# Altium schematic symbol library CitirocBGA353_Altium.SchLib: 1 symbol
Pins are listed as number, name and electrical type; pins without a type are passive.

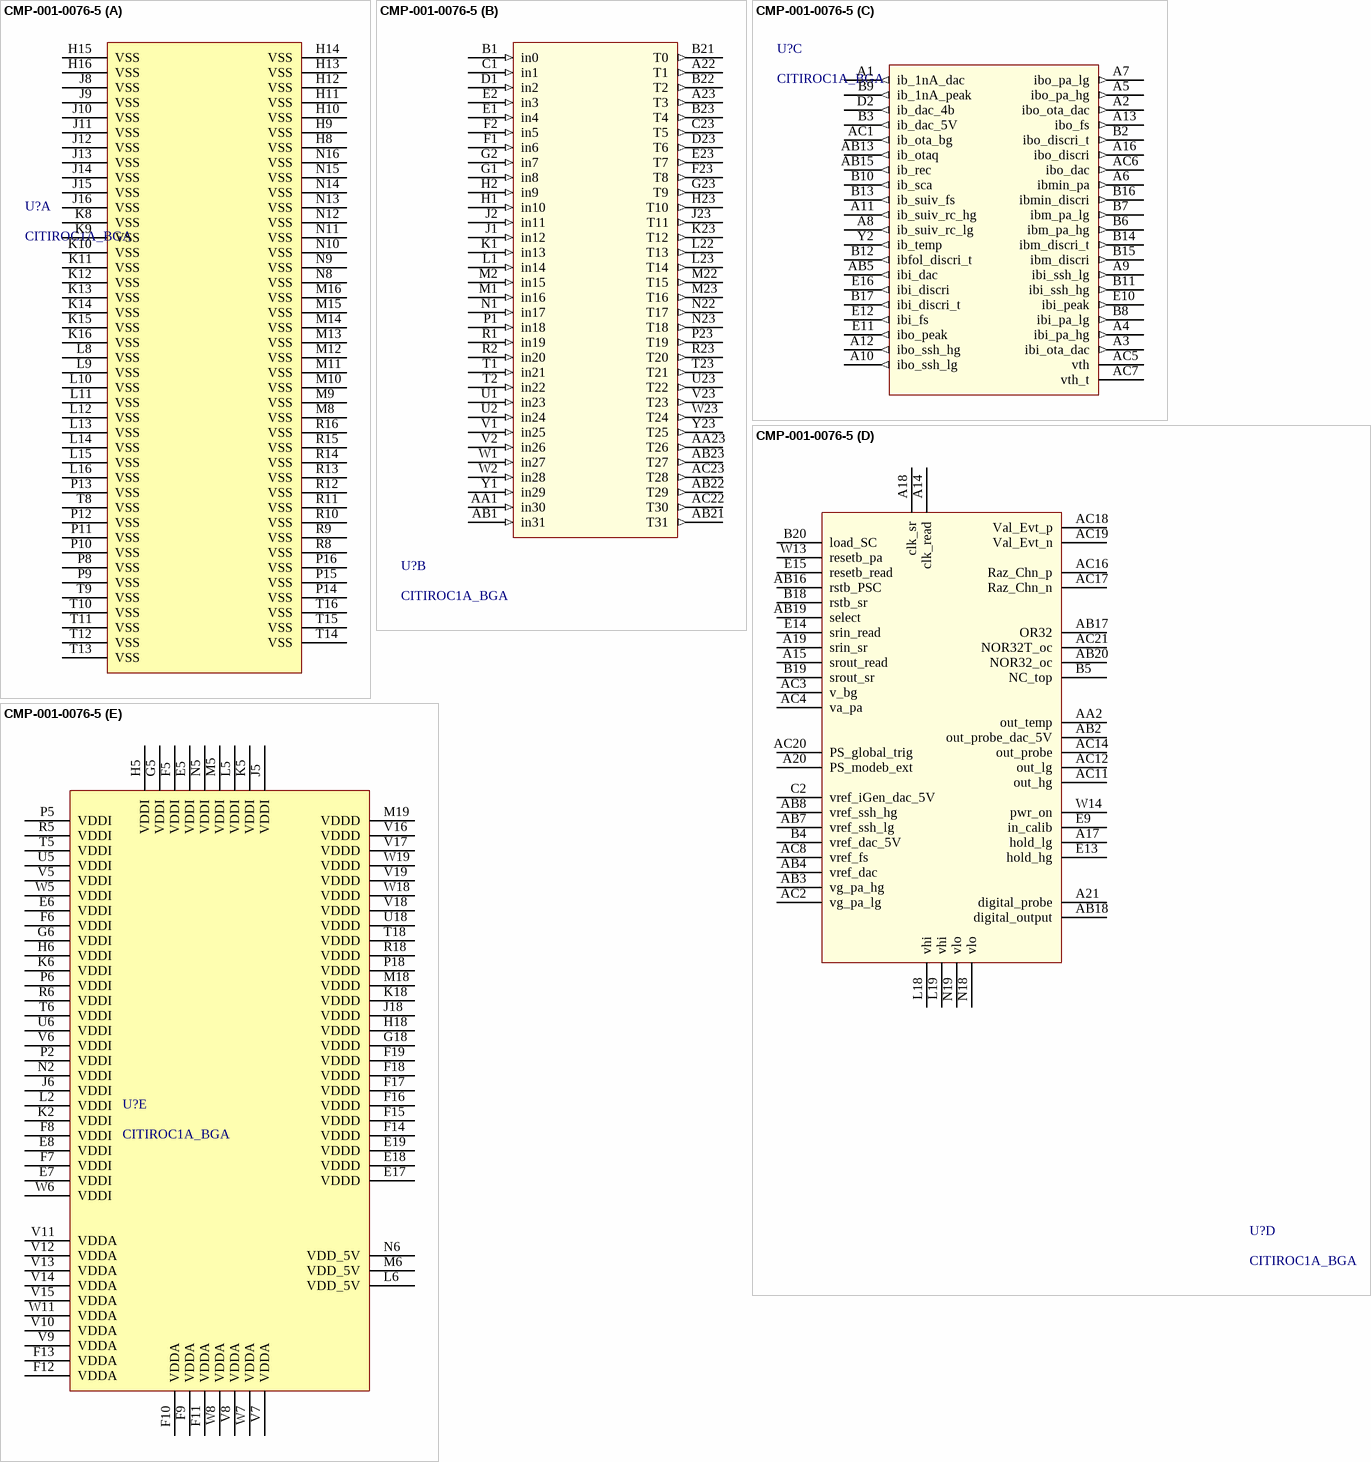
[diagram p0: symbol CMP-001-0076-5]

## CMP-001-0076-5
designator U?, comment CITIROC1A_BGA
Citiroc1A BGA
footprint BGA 353 12mmx12mm (BGA, 353-Leads, Body 12,00x12,00mmx1,20mm, Pitch 0,50mm)
part A pins: H8 VSS (power), H9 VSS (power), H10 VSS (power), H11 VSS (power), H12 VSS (power), H13 VSS (power), H14 VSS (power), H15 VSS (power), H16 VSS (power), J8 VSS (power), J9 VSS (power), J10 VSS (power), J11 VSS (power), J12 VSS (power), J13 VSS (power), J14 VSS (power), J15 VSS (power), J16 VSS (power), K8 VSS (power), K9 VSS (power), K10 VSS (power), K11 VSS (power), K12 VSS (power), K13 VSS (power), K14 VSS (power), K15 VSS (power), K16 VSS (power), L8 VSS (power), L9 VSS (power), L10 VSS (power), L11 VSS (power), L12 VSS (power), L13 VSS (power), L14 VSS (power), L15 VSS (power), L16 VSS (power), M8 VSS (power), M9 VSS (power), M10 VSS (power), M11 VSS (power), M12 VSS (power), M13 VSS (power), M14 VSS (power), M15 VSS (power), M16 VSS (power), N8 VSS (power), N9 VSS (power), N10 VSS (power), N11 VSS (power), N12 VSS (power), N13 VSS (power), N14 VSS (power), N15 VSS (power), N16 VSS (power), P8 VSS (power), P9 VSS (power), P10 VSS (power), P11 VSS (power), P12 VSS (power), P13 VSS (power), P14 VSS (power), P15 VSS (power), P16 VSS (power), R8 VSS (power), R9 VSS (power), R10 VSS (power), R11 VSS (power), R12 VSS (power), R13 VSS (power), R14 VSS (power), R15 VSS (power), R16 VSS (power), T8 VSS (power), T9 VSS (power), T10 VSS (power), T11 VSS (power), T12 VSS (power), T13 VSS (power), T14 VSS (power), T15 VSS (power), T16 VSS (power)
part B pins: A22 T1 (out), A23 T3 (out), AA1 in30 (in), AA23 T26 (out), AB1 in31 (in), AB21 T31 (out), AB22 T29 (out), AB23 T27 (out), AC22 T30 (out), AC23 T28 (out), B1 in0 (in), B21 T0 (out), B22 T2 (out), B23 T4 (out), C1 in1 (in), C23 T5 (out), D1 in2 (in), D23 T6 (out), E1 in4 (in), E2 in3 (in), E23 T7 (out), F1 in6 (in), F2 in5 (in), F23 T8 (out), G1 in8 (in), G2 in7 (in), G23 T9 (out), H1 in10 (in), H2 in9 (in), H23 T10 (out), J1 in12 (in), J2 in11 (in), J23 T11 (out), K1 in13 (in), K23 T12 (out), L1 in14 (in), L22 T13 (out), L23 T14 (out), M1 in16 (in), M2 in15 (in), M22 T15 (out), M23 T16 (out), N1 in17 (in), N22 T17 (out), N23 T18 (out), P1 in18 (in), P23 T19 (out), R1 in19 (in), R2 in20 (in), R23 T20 (out), T1 in21 (in), T2 in22 (in), T23 T21 (out), U1 in23 (in), U2 in24 (in), U23 T22 (out), V1 in25 (in), V2 in26 (in), V23 T23 (out), W1 in27 (in), W2 in28 (in), W23 T24 (out), Y1 in29 (in), Y23 T25 (out)
part C pins: A1 ib_1nA_dac (out), A2 ibo_ota_dac (out), A3 ibi_ota_dac (out), A4 ibi_pa_hg (out), A5 ibo_pa_hg (out), A6 ibmin_pa (out), A7 ibo_pa_lg (out), A8 ib_suiv_rc_lg (out), A9 ibi_ssh_lg (out), A10 ibo_ssh_lg (out), A11 ib_suiv_rc_hg (out), A12 ibo_ssh_hg (out), A13 ibo_fs (out), A16 ibo_discri (out), AB5 ibi_dac (out), AB13 ib_otaq (out), AB15 ib_rec (out), AC1 ib_ota_bg (out), AC5 vth, AC6 ibo_dac (out), AC7 vth_t, B2 ibo_discri_t (out), B3 ib_dac_5V (out), B6 ibm_pa_hg (out), B7 ibm_pa_lg (out), B8 ibi_pa_lg (out), B9 ib_1nA_peak (out), B10 ib_sca (out), B11 ibi_ssh_hg (out), B12 ibfol_discri_t (out), B13 ib_suiv_fs (out), B14 ibm_discri_t (out), B15 ibm_discri (out), B16 ibmin_discri (out), B17 ibi_discri_t (out), D2 ib_dac_4b (out), E10 ibi_peak (out), E11 ibo_peak (out), E12 ibi_fs (out), E16 ibi_discri (out), Y2 ib_temp (out)
part D pins: A14 clk_read, A15 srout_read, A17 hold_lg, A18 clk_sr, A19 srin_sr, A20 PS_modeb_ext, A21 digital_probe, AA2 out_temp, AB2 out_probe_dac_5V, AB3 vg_pa_hg, AB4 vref_dac, AB7 vref_ssh_lg, AB8 vref_ssh_hg, AB16 rstb_PSC, AB17 OR32, AB18 digital_output, AB19 select, AB20 NOR32_oc, AC2 vg_pa_lg, AC3 v_bg, AC4 va_pa, AC8 vref_fs, AC11 out_hg, AC12 out_lg, AC14 out_probe, AC16 Raz_Chn_p, AC17 Raz_Chn_n, AC18 Val_Evt_p, AC19 Val_Evt_n, AC20 PS_global_trig, AC21 NOR32T_oc, B4 vref_dac_5V, B5 NC_top, B18 rstb_sr, B19 srout_sr, B20 load_SC, C2 vref_iGen_dac_5V, E9 in_calib, E13 hold_hg, E14 srin_read, E15 resetb_read, L18 vhi, L19 vhi, N18 vlo, N19 vlo, W13 resetb_pa, W14 pwr_on
part E pins: E5 VDDI (power), E6 VDDI (power), E7 VDDI (power), E8 VDDI (power), E17 VDDD (power), E18 VDDD (power), E19 VDDD (power), F5 VDDI (power), F6 VDDI (power), F7 VDDI (power), F8 VDDI (power), F9 VDDA (power), F10 VDDA (power), F11 VDDA (power), F12 VDDA (power), F13 VDDA (power), F14 VDDD (power), F15 VDDD (power), F16 VDDD (power), F17 VDDD (power), F18 VDDD (power), F19 VDDD (power), G5 VDDI (power), G6 VDDI (power), G18 VDDD (power), H5 VDDI (power), H6 VDDI (power), H18 VDDD (power), J5 VDDI (power), J6 VDDI (power), J18 VDDD (power), K2 VDDI (power), K5 VDDI (power), K6 VDDI (power), K18 VDDD (power), L2 VDDI (power), L5 VDDI (power), L6 VDD_5V (power), M5 VDDI (power), M6 VDD_5V (power), M18 VDDD (power), M19 VDDD (power), N2 VDDI (power), N5 VDDI (power), N6 VDD_5V (power), P2 VDDI (power), P5 VDDI (power), P6 VDDI (power), P18 VDDD (power), R5 VDDI (power), R6 VDDI (power), R18 VDDD (power), T5 VDDI (power), T6 VDDI (power), T18 VDDD (power), U5 VDDI (power), U6 VDDI (power), U18 VDDD (power), V5 VDDI (power), V6 VDDI (power), V7 VDDA (power), V8 VDDA (power), V9 VDDA (power), V10 VDDA (power), V11 VDDA (power), V12 VDDA (power), V13 VDDA (power), V14 VDDA (power), V15 VDDA (power), V16 VDDD (power), V17 VDDD (power), V18 VDDD (power), V19 VDDD (power), W5 VDDI (power), W6 VDDI (power), W7 VDDA (power), W8 VDDA (power), W11 VDDA (power), W18 VDDD (power), W19 VDDD (power)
